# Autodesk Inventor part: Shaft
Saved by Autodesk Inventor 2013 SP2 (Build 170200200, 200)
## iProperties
Created: 2020-02
Part Number: Shaft
Material: Steel
Document SubType Name: Modeling
Designer: DELL
Density: 1 g/cm^3
CustomPartVersion: 1
Author: DELL
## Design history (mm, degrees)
sketch "Main Sketch"
  geometry: L1 (0, 0)-(18, 0) reference; L2 (0, 0)-(0, 2.5); L3 (18, 2.5)-(18, 0); L4 (0, 2.5)-(18, 2.5)
  constraints: 8 end point, 2 horizontal, 2 vertical
  dimensions: "d3" = 5 diameter of L4 L1 (derived)
revolve "Revolution1" sketch "Main Sketch" stored, may be unused: angle "d4" = 0 deg
chamfer "Chamfer4" distance "d14" = 0.25; stored, may be unused: second distance "d15" = 0.125, angle "d16" = 45 deg
node "Involute Splining1"
body "Solid1"
feature "Shaft Groove"
other parameters: "d0" = 0, "d1" = 0, "d2" = 0
